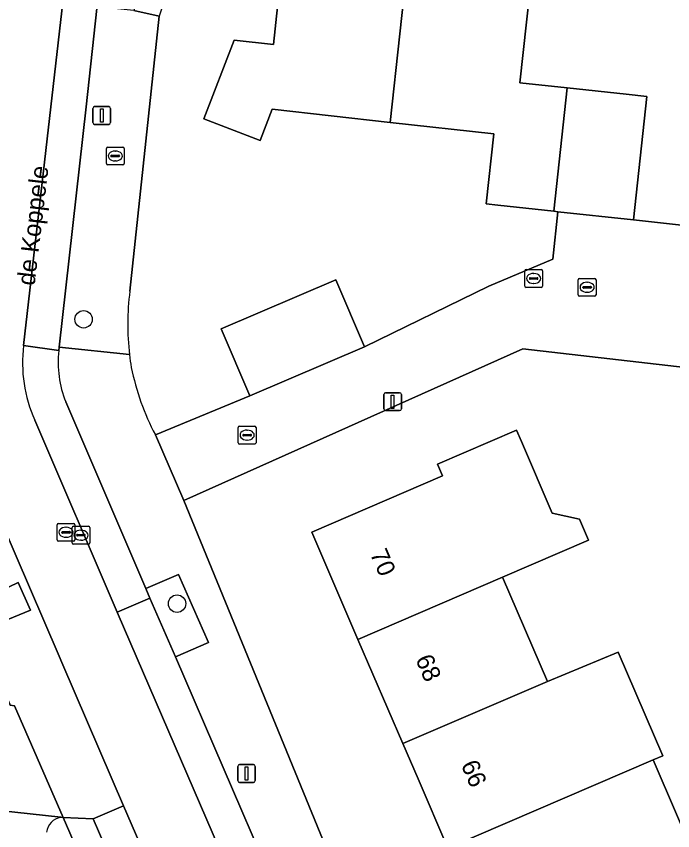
# Model space of a CAD drawing. Extents: x 162026 to 163502, y 387295 to 388169.
# Drawn here: x 162178.32 to 162215.28, y 387747.09 to 387792.93 of the extents above; entities that cross this region are included whole.
import ezdxf

# ---------------------------------------------------------------- set-up
doc = ezdxf.new("R2010")
doc.units = 0
for name, color, linetype in [('IMGEO_Boom', 7, 'Continuous'), ('IMGEO_Brandkraan', 7, 'Continuous'), ('IMGEO_Erf', 7, 'Continuous'), ('IMGEO_Groenvoorziening', 7, 'Continuous'), ('IMGEO_Kolk', 7, 'Continuous'), ('IMGEO_Lichtmast', 7, 'Continuous'), ('IMGEO_Openbare_ruimte_label', 7, 'Continuous'), ('IMGEO_Pand', 7, 'Continuous'), ('IMGEO_Pand_nummerreeks', 7, 'Continuous'), ('IMGEO_Parkeervlak_open', 7, 'Continuous'), ('IMGEO_Rijbaan_lokaal_open', 7, 'Continuous'), ('IMGEO_Rioolput', 7, 'Continuous'), ('IMGEO_Voetpad_gesloten', 7, 'Continuous'), ('IMGEO_Voetpad_open', 7, 'Continuous')]:
    doc.layers.add(name, color=color, linetype=linetype)

msp = doc.modelspace()

# ---------------------------------------------------------------- linework, layer by layer
at = {"layer": 'IMGEO_Boom'}
for centre in [(162182.108, 387775.872), (162187.369, 387759.868)]:
    msp.add_circle(centre, 0.489, dxfattribs=at)
at = {"layer": 'IMGEO_Brandkraan'}
for p, q in [((162183.464, 387785.565), (162184.316, 387785.565)), ((162183.389, 387784.639), (162183.389, 387785.491)), ((162183.691, 387785.108), (162184.089, 387785.108)), ((162183.877, 387785.345), (162183.902, 387785.345)), ((162184.39, 387785.491), (162184.39, 387784.639)), ((162183.648, 387785.059), (162183.648, 387785.071)), ((162184.086, 387785.022), (162183.688, 387785.022)), ((162183.9, 387784.785), (162183.875, 387784.785)), ((162184.132, 387785.071), (162184.132, 387785.059)), ((162184.316, 387784.565), (162183.464, 387784.565))]:
    msp.add_line(p, q, dxfattribs=at)
for points in [[(162183.464, 387785.565), (162184.316, 387785.565)], [(162183.389, 387784.639), (162183.389, 387785.491)], [(162184.39, 387785.491), (162184.39, 387784.639)], [(162184.316, 387784.565), (162183.464, 387784.565)]]:
    msp.add_lwpolyline(points, dxfattribs=at)
for centre, radius, start, end in [((162183.466, 387785.489), 0.0765, 91.552, 178.448), ((162183.466, 387785.489), 0.0765, 91.552, 178.448), ((162184.314, 387785.489), 0.0765, 1.552, 88.448), ((162184.314, 387785.489), 0.0765, 1.552, 88.448), ((162183.688, 387785.068), 0.0403, 85.8775, 175.7526), ((162184.093, 387785.07), 0.0386, 1.7309, 96.639), ((162183.466, 387784.641), 0.0765, 181.552, 268.448), ((162183.466, 387784.641), 0.0765, 181.552, 268.448), ((162183.685, 387785.058), 0.0366, 178.938, 274.7102), ((162184.089, 387785.065), 0.043, 264.8664, 352.4533), ((162184.314, 387784.641), 0.0765, 271.552, 358.448), ((162184.314, 387784.641), 0.0765, 271.552, 358.448)]:
    msp.add_arc(centre, radius, start, end, dxfattribs=at)
for centre, major_axis, ratio, start_param, end_param in [((162183.876, 387785.065), (-0.387, 0.002), 0.722429, 4.712389, 7.853982), ((162183.901, 387785.065), (-0.39, 0.002), 0.717154, 1.570796, 4.712389)]:
    msp.add_ellipse(centre, major_axis=major_axis, ratio=ratio, start_param=start_param, end_param=end_param, dxfattribs=at)
at = {"layer": 'IMGEO_Erf'}
for points in [[(162186.148, 387769.363), (162191.465, 387771.557), (162189.85, 387775.329), (162196.314, 387778.097), (162197.929, 387774.326), (162204.926, 387777.743), (162208.53, 387779.266), (162208.819, 387781.93), (162208.582, 387781.956), (162205.436, 387782.298), (162204.773, 387782.37), (162205.201, 387786.315), (162199.373, 387786.958), (162192.725, 387787.692), (162192.056, 387785.942), (162188.887, 387787.149), (162190.586, 387791.589), (162192.793, 387791.349), (162193.484, 387797.711)], [(162207.432, 387796.196), (162206.671, 387789.191), (162209.336, 387788.901), (162212.664, 387788.539), (162213.828, 387788.413), (162213.074, 387781.468), (162218.84, 387780.834), (162219.191, 387784.076), (162225.946, 387783.333), (162226.861, 387791.785), (162227.337, 387796.161)], [(162186.364, 387792.928), (162184.712, 387777.45)], [(162228.832, 387744.68), (162229.147, 387748.253), (162224.177, 387748.799), (162223.235, 387748.903), (162223.356, 387750), (162223.599, 387752.208), (162223.962, 387755.513), (162224.326, 387758.818), (162224.689, 387762.123), (162225.053, 387765.428), (162225.233, 387767.068), (162225.416, 387768.733), (162225.779, 387772.038), (162206.843, 387774.213), (162187.75, 387765.667), (162199.646, 387736.659)], [(162202.619, 387746.102), (162200.94, 387750), (162200.083, 387751.989), (162197.555, 387757.858), (162194.952, 387763.9), (162202.31, 387767.07), (162202.034, 387767.712), (162206.487, 387769.631), (162206.764, 387768.989), (162208.497, 387764.965), (162210.027, 387764.623), (162210.534, 387763.447), (162205.694, 387761.362), (162208.222, 387755.494), (162212.21, 387757.129), (162214.716, 387751.309), (162214.179, 387751.078), (162216.754, 387745.1)]]:
    msp.add_lwpolyline(points, dxfattribs=at)
for centre, radius, start, end in [((162199.766, 387789.126), 13.931, 116.6751, 164.161), ((162199.154, 387775.586), 14.562, 172.6473, 186.7098), ((162199.246, 387775.596), 14.654, 186.7061, 189.5541), ((162198.933, 387776.055), 14.431, 191.5578, 207.6295)]:
    msp.add_arc(centre, radius, start, end, dxfattribs=at)
at = {"layer": 'IMGEO_Groenvoorziening'}
for points in [[(162185.604, 387760.729), (162185.839, 387760.172), (162187.283, 387756.88), (162189.136, 387757.683), (162187.456, 387761.514)], [(162184.356, 387748.498), (162182.655, 387747.763), (162186.488, 387738.87), (162188.222, 387739.573)]]:
    msp.add_lwpolyline(points, close=True, dxfattribs=at)
for points in [[(162180.954, 387747.827), (162180.82, 387747.842)], [(162182.574, 387744.115), (162180.954, 387747.827)]]:
    msp.add_lwpolyline(points, dxfattribs=at)
msp.add_arc((162180.974, 387746.896), 0.958, 99.239, 173.3569, dxfattribs=at)
at = {"layer": 'IMGEO_Kolk'}
for p, q in [((162209.96, 387777.249), (162209.96, 387778.101)), ((162210.035, 387778.175), (162210.887, 387778.175)), ((162210.448, 387777.955), (162210.473, 387777.955)), ((162210.961, 387778.101), (162210.961, 387777.249)), ((162210.219, 387777.669), (162210.219, 387777.681)), ((162210.657, 387777.632), (162210.259, 387777.632)), ((162210.262, 387777.718), (162210.66, 387777.718)), ((162210.471, 387777.395), (162210.446, 387777.395)), ((162210.703, 387777.681), (162210.703, 387777.669)), ((162210.887, 387777.175), (162210.035, 387777.175)), ((162190.815, 387768.928), (162190.815, 387769.78)), ((162190.89, 387769.854), (162191.742, 387769.854)), ((162191.303, 387769.634), (162191.328, 387769.634)), ((162191.816, 387769.78), (162191.816, 387768.928)), ((162191.074, 387769.348), (162191.074, 387769.36)), ((162191.512, 387769.311), (162191.114, 387769.311)), ((162191.117, 387769.397), (162191.515, 387769.397)), ((162191.326, 387769.074), (162191.301, 387769.074)), ((162191.558, 387769.36), (162191.558, 387769.348)), ((162191.742, 387768.854), (162190.89, 387768.854)), ((162181.457, 387763.295), (162181.457, 387764.147)), ((162181.532, 387764.221), (162182.384, 387764.221)), ((162182.458, 387764.147), (162182.458, 387763.295)), ((162181.716, 387763.715), (162181.716, 387763.727)), ((162182.154, 387763.678), (162181.756, 387763.678)), ((162181.759, 387763.764), (162182.157, 387763.764)), ((162181.945, 387764.001), (162181.97, 387764.001)), ((162182.2, 387763.727), (162182.2, 387763.715)), ((162182.384, 387763.221), (162181.532, 387763.221)), ((162181.968, 387763.441), (162181.943, 387763.441))]:
    msp.add_line(p, q, dxfattribs=at)
for points in [[(162209.96, 387777.249), (162209.96, 387778.101)], [(162210.035, 387778.175), (162210.887, 387778.175)], [(162210.961, 387778.101), (162210.961, 387777.249)], [(162210.887, 387777.175), (162210.035, 387777.175)], [(162190.815, 387768.928), (162190.815, 387769.78)], [(162190.89, 387769.854), (162191.742, 387769.854)], [(162191.816, 387769.78), (162191.816, 387768.928)], [(162191.742, 387768.854), (162190.89, 387768.854)], [(162181.457, 387763.295), (162181.457, 387764.147)], [(162181.532, 387764.221), (162182.384, 387764.221)], [(162182.458, 387764.147), (162182.458, 387763.295)], [(162182.384, 387763.221), (162181.532, 387763.221)]]:
    msp.add_lwpolyline(points, dxfattribs=at)
for centre, radius, start, end in [((162210.037, 387778.099), 0.0765, 91.552, 178.448), ((162210.037, 387778.099), 0.0765, 91.552, 178.448), ((162210.885, 387778.099), 0.0765, 1.552, 88.448), ((162210.885, 387778.099), 0.0765, 1.552, 88.448), ((162210.259, 387777.678), 0.0403, 85.8775, 175.7526), ((162210.256, 387777.668), 0.0366, 178.938, 274.7102), ((162210.66, 387777.675), 0.043, 264.8664, 352.4533), ((162210.664, 387777.68), 0.0386, 1.7309, 96.639), ((162210.037, 387777.251), 0.0765, 181.552, 268.448), ((162210.037, 387777.251), 0.0765, 181.552, 268.448), ((162210.885, 387777.251), 0.0765, 271.552, 358.448), ((162210.885, 387777.251), 0.0765, 271.552, 358.448), ((162190.892, 387769.778), 0.0765, 91.552, 178.448), ((162190.892, 387769.778), 0.0765, 91.552, 178.448), ((162191.74, 387769.778), 0.0765, 1.552, 88.448), ((162191.74, 387769.778), 0.0765, 1.552, 88.448), ((162191.114, 387769.357), 0.0403, 85.8775, 175.7526), ((162191.111, 387769.347), 0.0366, 178.938, 274.7102), ((162191.515, 387769.354), 0.043, 264.8664, 352.4533), ((162191.519, 387769.359), 0.0386, 1.7309, 96.639), ((162190.892, 387768.93), 0.0765, 181.552, 268.448), ((162190.892, 387768.93), 0.0765, 181.552, 268.448), ((162191.74, 387768.93), 0.0765, 271.552, 358.448), ((162191.74, 387768.93), 0.0765, 271.552, 358.448), ((162181.534, 387764.145), 0.0765, 91.552, 178.448), ((162181.534, 387764.145), 0.0765, 91.552, 178.448), ((162182.382, 387764.145), 0.0765, 1.552, 88.448), ((162182.382, 387764.145), 0.0765, 1.552, 88.448), ((162181.756, 387763.724), 0.0403, 85.8775, 175.7526), ((162181.753, 387763.714), 0.0366, 178.938, 274.7102), ((162182.157, 387763.721), 0.043, 264.8664, 352.4533), ((162182.161, 387763.726), 0.0386, 1.7309, 96.639), ((162181.534, 387763.297), 0.0765, 181.552, 268.448), ((162181.534, 387763.297), 0.0765, 181.552, 268.448), ((162182.382, 387763.297), 0.0765, 271.552, 358.448), ((162182.382, 387763.297), 0.0765, 271.552, 358.448)]:
    msp.add_arc(centre, radius, start, end, dxfattribs=at)
for centre, major_axis, ratio, start_param, end_param in [((162210.447, 387777.675), (-0.387, 0.002), 0.722429, 4.712389, 7.853982), ((162210.472, 387777.675), (-0.39, 0.002), 0.717154, 1.570796, 4.712389), ((162191.302, 387769.354), (-0.387, 0.002), 0.722429, 4.712389, 7.853982), ((162191.327, 387769.354), (-0.39, 0.002), 0.717154, 1.570796, 4.712389), ((162181.944, 387763.721), (-0.387, 0.002), 0.722429, 4.712389, 7.853982), ((162181.969, 387763.721), (-0.39, 0.002), 0.717154, 1.570796, 4.712389)]:
    msp.add_ellipse(centre, major_axis=major_axis, ratio=ratio, start_param=start_param, end_param=end_param, dxfattribs=at)
at = {"layer": 'IMGEO_Lichtmast'}
for p, q in [((162182.631, 387786.942), (162182.631, 387787.742)), ((162182.631, 387787.742), (162182.631, 387786.942)), ((162182.731, 387787.842), (162183.521, 387787.842)), ((162183.521, 387787.842), (162182.731, 387787.842)), ((162183.621, 387787.742), (162183.621, 387786.942)), ((162183.621, 387786.942), (162183.621, 387787.742)), ((162183.521, 387786.842), (162182.731, 387786.842)), ((162182.731, 387786.842), (162183.521, 387786.842)), ((162199.013, 387770.837), (162199.013, 387771.637)), ((162199.013, 387771.637), (162199.013, 387770.837)), ((162199.113, 387771.737), (162199.903, 387771.737)), ((162199.903, 387771.737), (162199.113, 387771.737)), ((162200.003, 387771.637), (162200.003, 387770.837)), ((162200.003, 387770.837), (162200.003, 387771.637)), ((162199.903, 387770.737), (162199.113, 387770.737)), ((162199.113, 387770.737), (162199.903, 387770.737)), ((162190.888, 387750.811), (162191.678, 387750.811)), ((162191.678, 387750.811), (162190.888, 387750.811)), ((162190.788, 387749.911), (162190.788, 387750.711)), ((162190.788, 387750.711), (162190.788, 387749.911)), ((162191.778, 387750.711), (162191.778, 387749.911)), ((162191.778, 387749.911), (162191.778, 387750.711)), ((162191.678, 387749.811), (162190.888, 387749.811)), ((162190.888, 387749.811), (162191.678, 387749.811))]:
    msp.add_line(p, q, dxfattribs=at)
for points in [[(162183.051, 387787.717), (162183.201, 387787.717), (162183.201, 387786.967), (162183.051, 387786.967), (162183.051, 387787.717)], [(162199.433, 387771.612), (162199.583, 387771.612), (162199.583, 387770.862), (162199.433, 387770.862), (162199.433, 387771.612)], [(162191.208, 387750.686), (162191.358, 387750.686), (162191.358, 387749.936), (162191.208, 387749.936), (162191.208, 387750.686)]]:
    msp.add_lwpolyline(points, dxfattribs=at)
for centre, start, end in [((162182.731, 387787.742), 90, 180), ((162182.731, 387787.742), 90, 180), ((162183.521, 387787.742), 0, 90), ((162183.521, 387787.742), 360, 90), ((162182.731, 387786.942), 180, 270), ((162182.731, 387786.942), 180, 270), ((162183.521, 387786.942), 270, 0), ((162183.521, 387786.942), 270, 0), ((162199.113, 387771.637), 90, 180), ((162199.113, 387771.637), 90, 180), ((162199.903, 387771.637), 0, 90), ((162199.903, 387771.637), 360, 90), ((162199.113, 387770.837), 180, 270), ((162199.113, 387770.837), 180, 270), ((162199.903, 387770.837), 270, 0), ((162199.903, 387770.837), 270, 0), ((162190.888, 387750.711), 90, 180), ((162190.888, 387750.711), 90, 180), ((162191.678, 387750.711), 0, 90), ((162191.678, 387750.711), 360, 90), ((162190.888, 387749.911), 180, 270), ((162190.888, 387749.911), 180, 270), ((162191.678, 387749.911), 270, 0), ((162191.678, 387749.911), 270, 0)]:
    msp.add_arc(centre, 0.1, start, end, dxfattribs=at)
at = {"layer": 'IMGEO_Pand'}
for points in [[(162200.458, 387796.953), (162193.484, 387797.711), (162192.793, 387791.349), (162190.586, 387791.589), (162188.887, 387787.149), (162192.056, 387785.942), (162192.725, 387787.692), (162199.373, 387786.958)], [(162208.582, 387781.956), (162209.336, 387788.901), (162206.671, 387789.191), (162207.432, 387796.196), (162200.458, 387796.953), (162199.373, 387786.958), (162205.201, 387786.315), (162204.773, 387782.37), (162205.436, 387782.298)], [(162213.074, 387781.468), (162213.828, 387788.413), (162212.664, 387788.539), (162209.336, 387788.901), (162208.582, 387781.956), (162208.819, 387781.93)], [(162197.929, 387774.326), (162196.314, 387778.097), (162189.85, 387775.329), (162191.465, 387771.557)], [(162194.952, 387763.9), (162197.555, 387757.858), (162205.694, 387761.362), (162210.534, 387763.447), (162210.027, 387764.623), (162208.497, 387764.965), (162206.764, 387768.989), (162206.487, 387769.631), (162202.034, 387767.712), (162202.31, 387767.07)], [(162197.555, 387757.858), (162200.083, 387751.989), (162208.222, 387755.494), (162205.694, 387761.362)], [(162212.21, 387757.129), (162208.222, 387755.494), (162200.083, 387751.989), (162200.94, 387750), (162202.619, 387746.102), (162214.179, 387751.078), (162214.716, 387751.309)], [(162216.754, 387745.1), (162214.179, 387751.078), (162202.619, 387746.102), (162205.195, 387740.124)]]:
    msp.add_lwpolyline(points, close=True, dxfattribs=at)
at = {"layer": 'IMGEO_Parkeervlak_open'}
for points in [[(162182.252, 387787.828), (162182.857, 387793.357), (162180.964, 387793.918), (162178.729, 387774.397), (162180.708, 387774.113), (162180.732, 387774.305)], [(162194.687, 387739.718), (162192.64, 387744.402), (162192.658, 387744.41), (162187.283, 387756.88), (162185.839, 387760.172), (162184.007, 387759.385), (162190.837, 387743.58), (162199.088, 387724.536), (162200.438, 387721.412), (162220.431, 387675.156), (162222.246, 387675.933), (162220.958, 387678.949), (162219.135, 387683.064), (162215.688, 387691.083), (162213.663, 387695.793), (162208.525, 387707.663), (162206.489, 387712.379), (162201, 387725.104), (162198.978, 387729.758)]]:
    msp.add_lwpolyline(points, close=True, dxfattribs=at)
for points in [[(162180.708, 387774.113), (162178.729, 387774.397)], [(162179.355, 387770.201), (162184.007, 387759.385), (162185.839, 387760.172), (162185.604, 387760.729), (162181.102, 387771.227)], [(162180.82, 387747.842), (162146.618, 387751.565)]]:
    msp.add_lwpolyline(points, dxfattribs=at)
for centre, radius, start, end in [((162186.588, 387773.425), 7.919, 172.9484, 204.0223), ((162186.723, 387773.464), 6.049, 173.8433, 201.7047), ((162180.974, 387746.896), 0.958, 99.239, 173.3569)]:
    msp.add_arc(centre, radius, start, end, dxfattribs=at)
at = {"layer": 'IMGEO_Rijbaan_lokaal_open'}
for points in [[(162178.729, 387774.397), (162180.964, 387793.918)], [(162218.84, 387780.834), (162213.074, 387781.468), (162208.819, 387781.93), (162208.53, 387779.266), (162204.926, 387777.743), (162197.929, 387774.326), (162191.465, 387771.557), (162186.148, 387769.363), (162187.75, 387765.667), (162206.843, 387774.213), (162225.779, 387772.038)], [(162171.433, 387770.804), (162171.441, 387771.387), (162170.754, 387771.294), (162153.679, 387772.777), (162146.901, 387773.492), (162144.468, 387751.76), (162146.618, 387751.565), (162180.82, 387747.842), (162180.954, 387747.827), (162178.225, 387754.126), (162177.974, 387754.156), (162177.948, 387754.216)], [(162175.057, 387770.044), (162180.668, 387757.044), (162180.936, 387756.422), (162184.356, 387748.498), (162188.222, 387739.573), (162189.885, 387735.684), (162195.369, 387722.998), (162199.088, 387724.536), (162190.837, 387743.58), (162184.007, 387759.385), (162179.355, 387770.201)]]:
    msp.add_lwpolyline(points, dxfattribs=at)
msp.add_arc((162186.588, 387773.425), 7.919, 172.9484, 204.0223, dxfattribs=at)
at = {"layer": 'IMGEO_Rioolput'}
for p, q in [((162206.951, 387777.746), (162206.951, 387778.598)), ((162207.026, 387778.672), (162207.878, 387778.672)), ((162207.439, 387778.452), (162207.464, 387778.452)), ((162207.952, 387778.598), (162207.952, 387777.746)), ((162207.21, 387778.166), (162207.21, 387778.178)), ((162207.648, 387778.129), (162207.25, 387778.129)), ((162207.253, 387778.215), (162207.651, 387778.215)), ((162207.462, 387777.892), (162207.437, 387777.892)), ((162207.694, 387778.178), (162207.694, 387778.166)), ((162207.878, 387777.672), (162207.026, 387777.672)), ((162180.621, 387763.459), (162180.621, 387764.311)), ((162180.696, 387764.385), (162181.548, 387764.385)), ((162181.109, 387764.165), (162181.134, 387764.165)), ((162181.622, 387764.311), (162181.622, 387763.459)), ((162180.88, 387763.879), (162180.88, 387763.891)), ((162181.318, 387763.842), (162180.92, 387763.842)), ((162180.923, 387763.928), (162181.321, 387763.928)), ((162181.132, 387763.605), (162181.107, 387763.605)), ((162181.364, 387763.891), (162181.364, 387763.879)), ((162181.548, 387763.385), (162180.696, 387763.385))]:
    msp.add_line(p, q, dxfattribs=at)
for points in [[(162206.951, 387777.746), (162206.951, 387778.598)], [(162207.026, 387778.672), (162207.878, 387778.672)], [(162207.952, 387778.598), (162207.952, 387777.746)], [(162207.878, 387777.672), (162207.026, 387777.672)], [(162180.621, 387763.459), (162180.621, 387764.311)], [(162180.696, 387764.385), (162181.548, 387764.385)], [(162181.622, 387764.311), (162181.622, 387763.459)], [(162181.548, 387763.385), (162180.696, 387763.385)]]:
    msp.add_lwpolyline(points, dxfattribs=at)
for centre, radius, start, end in [((162207.028, 387778.596), 0.0765, 91.552, 178.448), ((162207.028, 387778.596), 0.0765, 91.552, 178.448), ((162207.876, 387778.596), 0.0765, 1.552, 88.448), ((162207.876, 387778.596), 0.0765, 1.552, 88.448), ((162207.25, 387778.175), 0.0403, 85.8775, 175.7526), ((162207.247, 387778.165), 0.0366, 178.938, 274.7102), ((162207.651, 387778.172), 0.043, 264.8664, 352.4533), ((162207.655, 387778.177), 0.0386, 1.7309, 96.639), ((162207.028, 387777.748), 0.0765, 181.552, 268.448), ((162207.028, 387777.748), 0.0765, 181.552, 268.448), ((162207.876, 387777.748), 0.0765, 271.552, 358.448), ((162207.876, 387777.748), 0.0765, 271.552, 358.448), ((162180.698, 387764.309), 0.0765, 91.552, 178.448), ((162180.698, 387764.309), 0.0765, 91.552, 178.448), ((162181.546, 387764.309), 0.0765, 1.552, 88.448), ((162181.546, 387764.309), 0.0765, 1.552, 88.448), ((162180.92, 387763.888), 0.0403, 85.8775, 175.7526), ((162180.917, 387763.878), 0.0366, 178.938, 274.7102), ((162181.321, 387763.885), 0.043, 264.8664, 352.4533), ((162181.325, 387763.89), 0.0386, 1.7309, 96.639), ((162180.698, 387763.461), 0.0765, 181.552, 268.448), ((162180.698, 387763.461), 0.0765, 181.552, 268.448), ((162181.546, 387763.461), 0.0765, 271.552, 358.448), ((162181.546, 387763.461), 0.0765, 271.552, 358.448)]:
    msp.add_arc(centre, radius, start, end, dxfattribs=at)
for centre, major_axis, ratio, start_param, end_param in [((162207.438, 387778.172), (-0.387, 0.002), 0.722429, 4.712389, 7.853982), ((162207.463, 387778.172), (-0.39, 0.002), 0.717154, 1.570796, 4.712389), ((162181.108, 387763.885), (-0.387, 0.002), 0.722429, 4.712389, 7.853982), ((162181.133, 387763.885), (-0.39, 0.002), 0.717154, 1.570796, 4.712389)]:
    msp.add_ellipse(centre, major_axis=major_axis, ratio=ratio, start_param=start_param, end_param=end_param, dxfattribs=at)
at = {"layer": 'IMGEO_Voetpad_gesloten'}
msp.add_lwpolyline([(162178.424, 387761.056), (162176.927, 387760.352), (162177.528, 387758.843), (162179.114, 387759.507)], close=True, dxfattribs=at)
at = {"layer": 'IMGEO_Voetpad_open'}
for points in [[(162185.254, 387794.309), (162184.931, 387793.25), (162186.364, 387792.928)], [(162186.364, 387792.928), (162184.931, 387793.25), (162183.098, 387793.438), (162182.857, 387793.357), (162182.252, 387787.828), (162180.732, 387774.305), (162184.692, 387773.885)], [(162184.712, 387777.45), (162186.364, 387792.928)], [(162184.692, 387773.885), (162180.732, 387774.305), (162180.708, 387774.113)], [(162181.102, 387771.227), (162185.604, 387760.729), (162187.456, 387761.514), (162189.136, 387757.683), (162187.283, 387756.88), (162192.658, 387744.41)], [(162171.984, 387768.129), (162173.502, 387764.542), (162173.513, 387764.515), (162177.948, 387754.216), (162177.974, 387754.156), (162178.225, 387754.126), (162180.954, 387747.827), (162182.655, 387747.763), (162184.356, 387748.498), (162180.936, 387756.422), (162180.668, 387757.044), (162175.057, 387770.044)], [(162187.75, 387765.667), (162186.148, 387769.363)], [(162223.576, 387682.288), (162214.757, 387702.428), (162213.749, 387704.73), (162209.626, 387714.146), (162199.646, 387736.659), (162187.75, 387765.667)], [(162205.878, 387698.65), (162204.156, 387697.934), (162198.251, 387711.7), (162199.955, 387712.383), (162198.263, 387716.306), (162196.55, 387715.597), (162188.179, 387734.99), (162189.885, 387735.684), (162188.222, 387739.573), (162186.488, 387738.87), (162182.655, 387747.763), (162180.954, 387747.827), (162182.574, 387744.115)]]:
    msp.add_lwpolyline(points, dxfattribs=at)
msp.add_lwpolyline([(162179.114, 387759.507), (162177.528, 387758.843), (162176.927, 387760.352), (162178.424, 387761.056)], close=True, dxfattribs=at)
for centre, radius, start, end in [((162199.766, 387789.126), 13.931, 116.6751, 164.161), ((162199.154, 387775.586), 14.562, 172.6473, 186.7098), ((162186.723, 387773.464), 6.049, 173.8433, 201.7047), ((162199.246, 387775.596), 14.654, 186.7061, 189.5541), ((162198.933, 387776.055), 14.431, 191.5578, 207.6295)]:
    msp.add_arc(centre, radius, start, end, dxfattribs=at)

# ---------------------------------------------------------------- texts
at = {"layer": 'IMGEO_Openbare_ruimte_label'}
msp.add_text('de Koppele', height=1, rotation=83.2801, dxfattribs=at).set_placement((162179.348, 387777.738))
at = {"layer": 'IMGEO_Pand_nummerreeks'}
for s, rotation, p in [('70', 293.3058, (162198.219, 387762.685)), ('68', 293.3058, (162200.777, 387756.747)), ('66', 293.3077, (162203.339, 387750.802))]:
    msp.add_text(s, height=1, rotation=rotation, dxfattribs=at).set_placement(p)

doc.saveas('drawing.dxf')
